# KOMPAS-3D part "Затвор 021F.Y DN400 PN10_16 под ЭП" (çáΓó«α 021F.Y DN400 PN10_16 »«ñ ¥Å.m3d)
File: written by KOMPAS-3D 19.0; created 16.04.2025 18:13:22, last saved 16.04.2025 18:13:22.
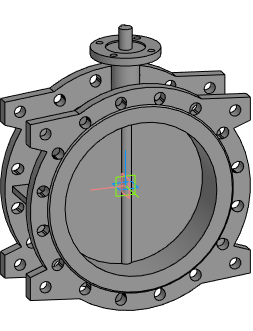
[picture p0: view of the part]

Document properties: Автор: Евгений; Полное имя файла: E:\Dendor Работа Сачек\3D для проекитирвщиков\1.6 Тип 021F.Y Затвор дисковый поворотный фланцевый\stp_Тип 021F.Y Затвор  DN40 PN10_16 под ЭП\Затвор 021F.Y DN400 PN10_16 под ЭП.m3d

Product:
- Part/product: Затвор 021F.Y DN400 PN10_16 под ЭП

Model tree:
1. Операция без истории:1  (labels: Затвор 021F.Y DN400 PN10_16 под ЭП)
